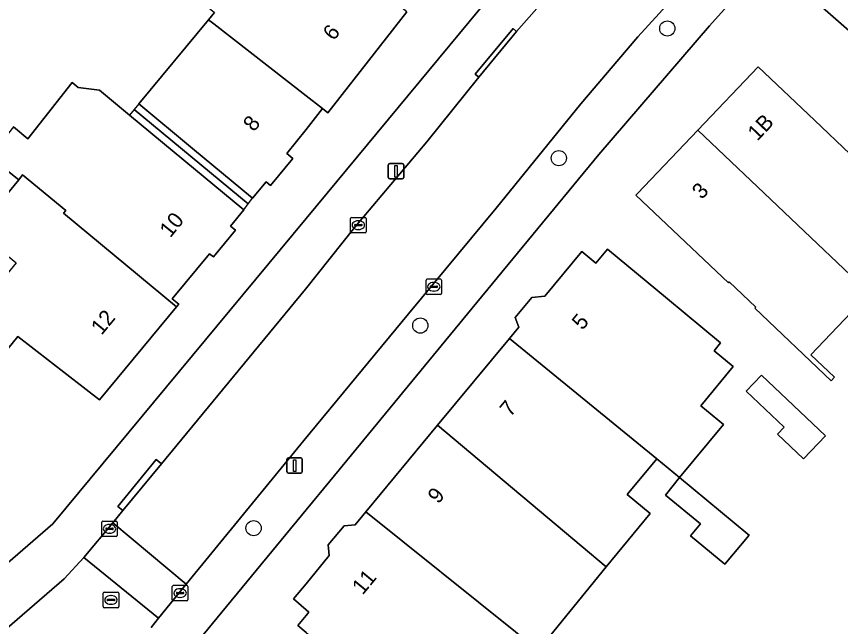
# Model space of a CAD drawing. Extents: x 161772 to 163126, y 383092 to 383917.
# Drawn here: x 162481.4 to 162534.3, y 383548.4 to 383587.6 of the extents above; entities that cross this region are included whole.
import ezdxf

# ---------------------------------------------------------------- set-up
doc = ezdxf.new("R2010")
doc.units = 0
for name, color, linetype in [('IMGEO_Boom', 7, 'Continuous'), ('IMGEO_Erf', 7, 'Continuous'), ('IMGEO_Kolk', 7, 'Continuous'), ('IMGEO_Lichtmast', 7, 'Continuous'), ('IMGEO_Pand', 7, 'Continuous'), ('IMGEO_Pand_nummerreeks', 7, 'Continuous'), ('IMGEO_Pand_overbouw', 7, 'Continuous'), ('IMGEO_Rijbaan_lokaal_open', 7, 'Continuous'), ('IMGEO_Rioolput', 7, 'Continuous'), ('IMGEO_Voetpad_open', 7, 'Continuous')]:
    doc.layers.add(name, color=color, linetype=linetype)

msp = doc.modelspace()

# ---------------------------------------------------------------- linework, layer by layer
at = {"layer": 'IMGEO_Boom'}
for centre in [(162523.191, 383586.794), (162516.227, 383578.471), (162507.334, 383567.722), (162496.634, 383554.71)]:
    msp.add_circle(centre, 0.489, dxfattribs=at)
at = {"layer": 'IMGEO_Erf'}
for points in [[(162462.704, 383536.779), (162483.744, 383554.98), (162500, 383574.599), (162526.947, 383607.122), (162543.804, 383623.317), (162548.918, 383628.126), (162539.791, 383641.093), (162527.133, 383641.683), (162527.105, 383641.456), (162500, 383642.583), (162442.25, 383644.984), (162375.184, 383528.714), (162418.191, 383500), (162425.357, 383495.215)], [(162539.703, 383602.034), (162533.89, 383595.873), (162525.907, 383586.964), (162518.786, 383578.702), (162510.666, 383568.842), (162501.518, 383557.733), (162500, 383555.89), (162492.693, 383547.017)], [(162506.472, 383587.872), (162501.403, 383581.38), (162501.06, 383581.651), (162500, 383580.313), (162498.774, 383578.766), (162499.16, 383578.446), (162497.723, 383576.713), (162497.439, 383576.949), (162496.57, 383575.901), (162492.72, 383579.092), (162489.265, 383581.957), (162493.744, 383587.36), (162494.132, 383587.828)], [(162481.216, 383580.476), (162482.14, 383579.711), (162484.991, 383583.321), (162485.376, 383583.002), (162486.746, 383582.836), (162488.671, 383581.24), (162492.165, 383578.343), (162496.014, 383575.152), (162495.15, 383574.109), (162495.473, 383573.841), (162494.053, 383572.128), (162493.8, 383572.337), (162491.399, 383569.44), (162491.827, 383569.086), (162491.689, 383568.92), (162486.735, 383562.944), (162481.496, 383567.012), (162479.628, 383564.76)], [(162478.866, 383573.829), (162481.566, 383577.087), (162479.686, 383578.547)], [(162500, 383548.023), (162499.466, 383548.469), (162500, 383549.112), (162500.175, 383549.323), (162500, 383549.474), (162499.194, 383550.167), (162500, 383551.142), (162501.492, 383552.948), (162501.427, 383553.635), (162502.443, 383554.862), (162503.146, 383554.928), (162503.842, 383555.768), (162508.448, 383561.33), (162513.053, 383566.891), (162513.652, 383567.614), (162513.423, 383568.23), (162514.493, 383569.521), (162515.331, 383569.6), (162517.71, 383572.472), (162518.611, 383571.727), (162519.349, 383572.618), (162523.2, 383569.429), (162526.612, 383566.602), (162526.193, 383566.096), (162527.417, 383565.082), (162525.341, 383562.575), (162526.799, 383561.367), (162523.978, 383557.962), (162522.513, 383559.16), (162520.617, 383556.87), (162522.095, 383555.647), (162519.266, 383552.231), (162515.623, 383547.758)]]:
    msp.add_lwpolyline(points, dxfattribs=at)
for points in [[(162544.222, 383584.846), (162541.032, 383581.223), (162536.404, 383585.298), (162532.651, 383588.602), (162539.681, 383596.585), (162543.434, 383593.281), (162548.075, 383589.194), (162546.474, 383587.375), (162546.712, 383586.669), (162544.973, 383584.695)], [(162537.296, 383568.725), (162536.236, 383569.732), (162536.189, 383569.682), (162537.629, 383568.313), (162537.354, 383568.023), (162535.847, 383569.455), (162532.415, 383565.845), (162533.932, 383564.403), (162533.718, 383564.179), (162528.818, 383568.836), (162528.88, 383568.901), (162527.172, 383570.524), (162527.11, 383570.459), (162521.181, 383576.094), (162521.277, 383576.194), (162525.149, 383580.269), (162529.02, 383584.344), (162532.645, 383580.901), (162534.926, 383578.733), (162537.177, 383576.596), (162536.914, 383576.319), (162540.936, 383572.495)], [(162530.268, 383560.751), (162530.684, 383561.191), (162528.246, 383563.502), (162529.232, 383564.543), (162533.346, 383560.643), (162531.943, 383559.163)], [(162523.978, 383557.962), (162528.354, 383554.327), (162528.437, 383554.27), (162526.88, 383552.39), (162524.68, 383554.212), (162525.322, 383554.987), (162523.084, 383556.841)]]:
    msp.add_lwpolyline(points, close=True, dxfattribs=at)
at = {"layer": 'IMGEO_Kolk'}
for p, q in [((162502.858, 383573.743), (162502.858, 383574.595)), ((162502.933, 383574.669), (162503.785, 383574.669)), ((162503.117, 383574.163), (162503.117, 383574.175)), ((162503.16, 383574.212), (162503.558, 383574.212)), ((162503.346, 383574.449), (162503.371, 383574.449)), ((162503.601, 383574.175), (162503.601, 383574.163)), ((162503.859, 383574.595), (162503.859, 383573.743)), ((162503.785, 383573.669), (162502.933, 383573.669)), ((162503.555, 383574.126), (162503.157, 383574.126)), ((162503.369, 383573.889), (162503.344, 383573.889)), ((162507.704, 383569.785), (162507.704, 383570.637)), ((162507.779, 383570.711), (162508.631, 383570.711)), ((162508.192, 383570.491), (162508.217, 383570.491)), ((162508.705, 383570.637), (162508.705, 383569.785)), ((162507.963, 383570.205), (162507.963, 383570.217)), ((162508.401, 383570.168), (162508.003, 383570.168)), ((162508.006, 383570.254), (162508.404, 383570.254)), ((162508.215, 383569.931), (162508.19, 383569.931)), ((162508.447, 383570.217), (162508.447, 383570.205)), ((162508.631, 383569.711), (162507.779, 383569.711)), ((162486.956, 383555.169), (162487.808, 383555.169)), ((162486.881, 383554.243), (162486.881, 383555.095)), ((162487.14, 383554.663), (162487.14, 383554.675)), ((162487.578, 383554.626), (162487.18, 383554.626)), ((162487.183, 383554.712), (162487.581, 383554.712)), ((162487.369, 383554.949), (162487.394, 383554.949)), ((162487.624, 383554.675), (162487.624, 383554.663)), ((162487.882, 383555.095), (162487.882, 383554.243)), ((162487.808, 383554.169), (162486.956, 383554.169)), ((162487.392, 383554.389), (162487.367, 383554.389)), ((162491.415, 383550.116), (162491.415, 383550.968)), ((162491.49, 383551.042), (162492.342, 383551.042)), ((162492.416, 383550.968), (162492.416, 383550.116)), ((162491.674, 383550.536), (162491.674, 383550.548)), ((162492.112, 383550.499), (162491.714, 383550.499)), ((162491.717, 383550.585), (162492.115, 383550.585)), ((162491.903, 383550.822), (162491.928, 383550.822)), ((162492.158, 383550.548), (162492.158, 383550.536)), ((162492.342, 383550.042), (162491.49, 383550.042)), ((162491.926, 383550.262), (162491.901, 383550.262))]:
    msp.add_line(p, q, dxfattribs=at)
for points in [[(162502.858, 383573.743), (162502.858, 383574.595)], [(162502.933, 383574.669), (162503.785, 383574.669)], [(162503.859, 383574.595), (162503.859, 383573.743)], [(162503.785, 383573.669), (162502.933, 383573.669)], [(162507.704, 383569.785), (162507.704, 383570.637)], [(162507.779, 383570.711), (162508.631, 383570.711)], [(162508.705, 383570.637), (162508.705, 383569.785)], [(162508.631, 383569.711), (162507.779, 383569.711)], [(162486.956, 383555.169), (162487.808, 383555.169)], [(162486.881, 383554.243), (162486.881, 383555.095)], [(162487.882, 383555.095), (162487.882, 383554.243)], [(162487.808, 383554.169), (162486.956, 383554.169)], [(162491.415, 383550.116), (162491.415, 383550.968)], [(162491.49, 383551.042), (162492.342, 383551.042)], [(162492.416, 383550.968), (162492.416, 383550.116)], [(162492.342, 383550.042), (162491.49, 383550.042)]]:
    msp.add_lwpolyline(points, dxfattribs=at)
for centre, radius, start, end in [((162502.935, 383574.593), 0.0765, 91.552, 178.448), ((162502.935, 383574.593), 0.0765, 91.552, 178.448), ((162503.157, 383574.172), 0.0403, 85.8775, 175.7526), ((162503.154, 383574.162), 0.0366, 178.938, 274.7102), ((162503.558, 383574.169), 0.043, 264.8664, 352.4533), ((162503.562, 383574.174), 0.0386, 1.7309, 96.639), ((162503.783, 383574.593), 0.0765, 1.552, 88.448), ((162503.783, 383574.593), 0.0765, 1.552, 88.448), ((162502.935, 383573.745), 0.0765, 181.552, 268.448), ((162502.935, 383573.745), 0.0765, 181.552, 268.448), ((162503.783, 383573.745), 0.0765, 271.552, 358.448), ((162503.783, 383573.745), 0.0765, 271.552, 358.448), ((162507.781, 383570.635), 0.0765, 91.552, 178.448), ((162507.781, 383570.635), 0.0765, 91.552, 178.448), ((162508.629, 383570.635), 0.0765, 1.552, 88.448), ((162508.629, 383570.635), 0.0765, 1.552, 88.448), ((162508.003, 383570.214), 0.0403, 85.8775, 175.7526), ((162508, 383570.204), 0.0366, 178.938, 274.7102), ((162508.404, 383570.211), 0.043, 264.8664, 352.4533), ((162508.408, 383570.216), 0.0386, 1.7309, 96.639), ((162507.781, 383569.787), 0.0765, 181.552, 268.448), ((162507.781, 383569.787), 0.0765, 181.552, 268.448), ((162508.629, 383569.787), 0.0765, 271.552, 358.448), ((162508.629, 383569.787), 0.0765, 271.552, 358.448), ((162486.958, 383555.093), 0.0765, 91.552, 178.448), ((162486.958, 383555.093), 0.0765, 91.552, 178.448), ((162487.806, 383555.093), 0.0765, 1.552, 88.448), ((162487.806, 383555.093), 0.0765, 1.552, 88.448), ((162487.18, 383554.672), 0.0403, 85.8775, 175.7526), ((162487.177, 383554.662), 0.0366, 178.938, 274.7102), ((162487.581, 383554.669), 0.043, 264.8664, 352.4533), ((162487.585, 383554.674), 0.0386, 1.7309, 96.639), ((162486.958, 383554.245), 0.0765, 181.552, 268.448), ((162486.958, 383554.245), 0.0765, 181.552, 268.448), ((162487.806, 383554.245), 0.0765, 271.552, 358.448), ((162487.806, 383554.245), 0.0765, 271.552, 358.448), ((162491.492, 383550.966), 0.0765, 91.552, 178.448), ((162491.492, 383550.966), 0.0765, 91.552, 178.448), ((162492.34, 383550.966), 0.0765, 1.552, 88.448), ((162492.34, 383550.966), 0.0765, 1.552, 88.448), ((162491.714, 383550.545), 0.0403, 85.8775, 175.7526), ((162491.711, 383550.535), 0.0366, 178.938, 274.7102), ((162492.115, 383550.542), 0.043, 264.8664, 352.4533), ((162492.119, 383550.547), 0.0386, 1.7309, 96.639), ((162491.492, 383550.118), 0.0765, 181.552, 268.448), ((162491.492, 383550.118), 0.0765, 181.552, 268.448), ((162492.34, 383550.118), 0.0765, 271.552, 358.448), ((162492.34, 383550.118), 0.0765, 271.552, 358.448)]:
    msp.add_arc(centre, radius, start, end, dxfattribs=at)
for centre, major_axis, ratio, start_param, end_param in [((162503.345, 383574.169), (-0.387, 0.002), 0.722429, 4.712389, 7.853982), ((162503.37, 383574.169), (-0.39, 0.002), 0.717154, 1.570796, 4.712389), ((162508.191, 383570.211), (-0.387, 0.002), 0.722429, 4.712389, 7.853982), ((162508.216, 383570.211), (-0.39, 0.002), 0.717154, 1.570796, 4.712389), ((162487.368, 383554.669), (-0.387, 0.002), 0.722429, 4.712389, 7.853982), ((162487.393, 383554.669), (-0.39, 0.002), 0.717154, 1.570796, 4.712389), ((162491.902, 383550.542), (-0.387, 0.002), 0.722429, 4.712389, 7.853982), ((162491.927, 383550.542), (-0.39, 0.002), 0.717154, 1.570796, 4.712389)]:
    msp.add_ellipse(centre, major_axis=major_axis, ratio=ratio, start_param=start_param, end_param=end_param, dxfattribs=at)
at = {"layer": 'IMGEO_Lichtmast'}
for p, q in [((162505.279, 383577.234), (162505.279, 383578.034)), ((162505.279, 383578.034), (162505.279, 383577.234)), ((162505.379, 383578.134), (162506.169, 383578.134)), ((162506.169, 383578.134), (162505.379, 383578.134)), ((162506.269, 383578.034), (162506.269, 383577.234)), ((162506.269, 383577.234), (162506.269, 383578.034)), ((162506.169, 383577.134), (162505.379, 383577.134)), ((162505.379, 383577.134), (162506.169, 383577.134)), ((162498.771, 383558.334), (162498.771, 383559.134)), ((162498.771, 383559.134), (162498.771, 383558.334)), ((162498.871, 383559.234), (162499.661, 383559.234)), ((162499.661, 383559.234), (162498.871, 383559.234)), ((162499.761, 383559.134), (162499.761, 383558.334)), ((162499.761, 383558.334), (162499.761, 383559.134)), ((162499.661, 383558.234), (162498.871, 383558.234)), ((162498.871, 383558.234), (162499.661, 383558.234))]:
    msp.add_line(p, q, dxfattribs=at)
for points in [[(162505.699, 383578.009), (162505.849, 383578.009), (162505.849, 383577.259), (162505.699, 383577.259), (162505.699, 383578.009)], [(162499.191, 383559.109), (162499.341, 383559.109), (162499.341, 383558.359), (162499.191, 383558.359), (162499.191, 383559.109)]]:
    msp.add_lwpolyline(points, dxfattribs=at)
for centre, start, end in [((162505.379, 383578.034), 90, 180), ((162505.379, 383578.034), 90, 180), ((162506.169, 383578.034), 0, 90), ((162506.169, 383578.034), 360, 90), ((162505.379, 383577.234), 180, 270), ((162505.379, 383577.234), 180, 270), ((162506.169, 383577.234), 270, 0), ((162506.169, 383577.234), 270, 0), ((162498.871, 383559.134), 90, 180), ((162498.871, 383559.134), 90, 180), ((162499.661, 383559.134), 0, 90), ((162499.661, 383559.134), 360, 90), ((162498.871, 383558.334), 180, 270), ((162498.871, 383558.334), 180, 270), ((162499.661, 383558.334), 270, 0), ((162499.661, 383558.334), 270, 0)]:
    msp.add_arc(centre, 0.1, start, end, dxfattribs=at)
at = {"layer": 'IMGEO_Pand'}
for points in [[(162504.664, 383590.902), (162501.958, 383593.04), (162503.741, 383595.297), (162500, 383598.256), (162499.797, 383598.417), (162497.67, 383600.132), (162498.544, 383601.187), (162492.309, 383605.412), (162489.661, 383602.217), (162495.432, 383597.433), (162494.746, 383596.605), (162496.763, 383594.932), (162492.201, 383589.429), (162494.132, 383587.828), (162493.744, 383587.36), (162494.073, 383587.101), (162500, 383582.475), (162501.06, 383581.651), (162501.403, 383581.38), (162506.472, 383587.872), (162503.885, 383589.916)], [(162541.032, 383581.223), (162544.222, 383584.846), (162544.973, 383584.695), (162546.712, 383586.669), (162546.474, 383587.375), (162548.075, 383589.194), (162543.434, 383593.281), (162539.681, 383596.585), (162532.651, 383588.602), (162536.404, 383585.298)], [(162493.744, 383587.36), (162489.265, 383581.957), (162492.72, 383579.092), (162496.57, 383575.901), (162497.439, 383576.949), (162497.723, 383576.713), (162499.16, 383578.446), (162498.774, 383578.766), (162500, 383580.313), (162501.06, 383581.651), (162500, 383582.475), (162494.073, 383587.101)], [(162536.236, 383569.732), (162537.296, 383568.725), (162540.936, 383572.495), (162536.914, 383576.319), (162537.177, 383576.596), (162534.926, 383578.733), (162532.645, 383580.901), (162529.02, 383584.344), (162525.149, 383580.269)], [(162491.689, 383568.92), (162491.827, 383569.086), (162491.399, 383569.44), (162493.8, 383572.337), (162494.053, 383572.128), (162495.473, 383573.841), (162495.15, 383574.109), (162496.014, 383575.152), (162492.165, 383578.343), (162488.671, 383581.24), (162486.746, 383582.836), (162485.376, 383583.002), (162484.991, 383583.321), (162482.14, 383579.711), (162481.216, 383580.476), (162479.686, 383578.547), (162481.566, 383577.087), (162481.806, 383577.39), (162484.569, 383575.1), (162484.436, 383574.932)], [(162525.149, 383580.269), (162521.277, 383576.194), (162521.181, 383576.094), (162527.11, 383570.459), (162527.172, 383570.524), (162528.88, 383568.901), (162528.818, 383568.836), (162533.718, 383564.179), (162533.932, 383564.403), (162532.415, 383565.845), (162535.847, 383569.455), (162537.354, 383568.023), (162537.629, 383568.313), (162536.189, 383569.682), (162536.236, 383569.732)], [(162491.689, 383568.92), (162484.436, 383574.932), (162484.569, 383575.1), (162481.806, 383577.39), (162481.566, 383577.087), (162478.866, 383573.829), (162481.383, 383571.745), (162479.42, 383569.376), (162477.097, 383571.301), (162476.648, 383571.673), (162473.721, 383568.14), (162476.216, 383565.042), (162477.407, 383566.479), (162479.628, 383564.76), (162481.496, 383567.012), (162486.735, 383562.944)], [(162523.2, 383569.429), (162519.349, 383572.618), (162518.611, 383571.727), (162517.71, 383572.472), (162515.331, 383569.6), (162514.493, 383569.521), (162513.423, 383568.23), (162513.652, 383567.614), (162513.053, 383566.891), (162522.513, 383559.16), (162523.978, 383557.962), (162526.799, 383561.367), (162525.341, 383562.575), (162527.417, 383565.082), (162526.193, 383566.096), (162526.612, 383566.602)], [(162522.513, 383559.16), (162513.053, 383566.891), (162508.448, 383561.33), (162519.266, 383552.231), (162522.095, 383555.647), (162520.617, 383556.87)], [(162531.943, 383559.163), (162533.346, 383560.643), (162529.232, 383564.543), (162528.246, 383563.502), (162530.684, 383561.191), (162530.268, 383560.751)], [(162508.448, 383561.33), (162503.842, 383555.768), (162513.455, 383548.049), (162514.883, 383546.865), (162515.623, 383547.758), (162519.266, 383552.231)], [(162523.978, 383557.962), (162523.084, 383556.841), (162525.322, 383554.987), (162524.68, 383554.212), (162526.88, 383552.39), (162528.437, 383554.27), (162528.354, 383554.327)], [(162503.842, 383555.768), (162503.146, 383554.928), (162502.443, 383554.862), (162501.427, 383553.635), (162501.492, 383552.948), (162500, 383551.142), (162499.194, 383550.167), (162500, 383549.474), (162500.175, 383549.323), (162500, 383549.112), (162499.466, 383548.469), (162500, 383548.023), (162503.265, 383545.293), (162506.761, 383542.365), (162509.345, 383540.203), (162511.12, 383542.324), (162514.671, 383546.609), (162514.883, 383546.865), (162513.455, 383548.049)]]:
    msp.add_lwpolyline(points, close=True, dxfattribs=at)
at = {"layer": 'IMGEO_Pand_overbouw'}
for points in [[(162488.671, 383581.24), (162492.165, 383578.343), (162496.014, 383575.152), (162496.292, 383575.527), (162488.968, 383581.599)], [(162489.265, 383581.957), (162488.968, 383581.599), (162496.292, 383575.527), (162496.57, 383575.901), (162492.72, 383579.092)]]:
    msp.add_lwpolyline(points, close=True, dxfattribs=at)
at = {"layer": 'IMGEO_Rijbaan_lokaal_open'}
for points in [[(162537.203, 383612.786), (162532.418, 383607.776), (162527.435, 383602.384), (162520.458, 383594.506), (162513.52, 383586.607), (162511.095, 383583.664), (162507.749, 383579.508), (162503.132, 383574.038), (162499.96, 383570.06), (162490.713, 383558.838), (162488.243, 383555.841), (162487.591, 383555.051), (162492.315, 383551.109), (162499.866, 383560.331), (162506.576, 383568.47), (162512.205, 383575.261), (162517.639, 383581.965), (162521.297, 383586.253), (162525.402, 383590.777), (162527.89, 383593.519), (162530.565, 383596.403), (162537.488, 383604.096)], [(162490.049, 383548.342), (162490.534, 383548.934), (162485.735, 383552.822), (162484.483, 383551.467), (162468.577, 383537.721)]]:
    msp.add_lwpolyline(points, dxfattribs=at)
msp.add_lwpolyline([(162487.591, 383555.051), (162485.735, 383552.822), (162490.534, 383548.934), (162492.315, 383551.109)], close=True, dxfattribs=at)
at = {"layer": 'IMGEO_Rioolput'}
for p, q in [((162486.973, 383549.679), (162486.973, 383550.531)), ((162487.048, 383550.605), (162487.9, 383550.605)), ((162487.461, 383550.385), (162487.486, 383550.385)), ((162487.974, 383550.531), (162487.974, 383549.679)), ((162487.232, 383550.099), (162487.232, 383550.111)), ((162487.67, 383550.062), (162487.272, 383550.062)), ((162487.275, 383550.148), (162487.673, 383550.148)), ((162487.484, 383549.825), (162487.459, 383549.825)), ((162487.716, 383550.111), (162487.716, 383550.099)), ((162487.9, 383549.605), (162487.048, 383549.605))]:
    msp.add_line(p, q, dxfattribs=at)
for points in [[(162486.973, 383549.679), (162486.973, 383550.531)], [(162487.048, 383550.605), (162487.9, 383550.605)], [(162487.974, 383550.531), (162487.974, 383549.679)], [(162487.9, 383549.605), (162487.048, 383549.605)]]:
    msp.add_lwpolyline(points, dxfattribs=at)
for centre, radius, start, end in [((162487.05, 383550.529), 0.0765, 91.552, 178.448), ((162487.05, 383550.529), 0.0765, 91.552, 178.448), ((162487.898, 383550.529), 0.0765, 1.552, 88.448), ((162487.898, 383550.529), 0.0765, 1.552, 88.448), ((162487.272, 383550.108), 0.0403, 85.8775, 175.7526), ((162487.269, 383550.098), 0.0366, 178.938, 274.7102), ((162487.673, 383550.105), 0.043, 264.8664, 352.4533), ((162487.677, 383550.11), 0.0386, 1.7309, 96.639), ((162487.05, 383549.681), 0.0765, 181.552, 268.448), ((162487.05, 383549.681), 0.0765, 181.552, 268.448), ((162487.898, 383549.681), 0.0765, 271.552, 358.448), ((162487.898, 383549.681), 0.0765, 271.552, 358.448)]:
    msp.add_arc(centre, radius, start, end, dxfattribs=at)
for centre, major_axis, ratio, start_param, end_param in [((162487.46, 383550.105), (-0.387, 0.002), 0.722429, 4.712389, 7.853982), ((162487.485, 383550.105), (-0.39, 0.002), 0.717154, 1.570796, 4.712389)]:
    msp.add_ellipse(centre, major_axis=major_axis, ratio=ratio, start_param=start_param, end_param=end_param, dxfattribs=at)
at = {"layer": 'IMGEO_Voetpad_open'}
for points in [[(162549.66, 383629.858), (162548.918, 383628.126), (162543.804, 383623.317), (162526.947, 383607.122), (162500, 383574.599), (162483.744, 383554.98), (162462.704, 383536.779), (162467.807, 383530.859), (162432.045, 383500), (162426.613, 383495.312), (162428.778, 383494.029), (162435.72, 383500), (162437.045, 383501.14), (162437.192, 383501.282), (162438.691, 383502.574), (162438.438, 383502.865), (162441.394, 383505.425), (162441.654, 383505.126), (162443.112, 383506.379), (162469.395, 383528.971)], [(162468.577, 383537.721), (162484.483, 383551.467), (162485.735, 383552.822), (162487.591, 383555.051), (162488.243, 383555.841), (162487.915, 383556.108), (162490.371, 383559.116), (162490.713, 383558.838), (162499.96, 383570.06), (162503.132, 383574.038), (162507.749, 383579.508), (162511.095, 383583.664), (162510.859, 383583.859), (162513.286, 383586.801), (162513.52, 383586.607), (162520.458, 383594.506), (162527.435, 383602.384), (162532.418, 383607.776), (162537.203, 383612.786), (162540.103, 383615.776), (162538.984, 383617.258), (162540.462, 383618.813), (162542.308, 383616.755)], [(162497.729, 383541.518), (162492.693, 383547.017), (162500, 383555.89), (162501.518, 383557.733), (162510.666, 383568.842), (162518.786, 383578.702), (162525.907, 383586.964), (162533.89, 383595.873), (162539.703, 383602.034), (162537.488, 383604.096), (162530.565, 383596.403), (162527.89, 383593.519), (162528.327, 383593.13), (162525.868, 383590.36), (162525.402, 383590.777), (162521.297, 383586.253), (162517.639, 383581.965), (162512.205, 383575.261), (162506.576, 383568.47), (162499.866, 383560.331), (162492.315, 383551.109), (162490.534, 383548.934), (162490.049, 383548.342)]]:
    msp.add_lwpolyline(points, dxfattribs=at)
for points in [[(162513.52, 383586.607), (162513.286, 383586.801), (162510.859, 383583.859), (162511.095, 383583.664)], [(162490.713, 383558.838), (162490.371, 383559.116), (162487.915, 383556.108), (162488.243, 383555.841)]]:
    msp.add_lwpolyline(points, close=True, dxfattribs=at)

# ---------------------------------------------------------------- texts
at = {"layer": 'IMGEO_Pand_nummerreeks'}
for s, rotation, p in [('6', 52.0188, (162501.782, 383585.961)), ('8', 52.0148, (162496.661, 383580.114)), ('1B', 46.467, (162528.971, 383579.53)), ('3', 46.4669, (162525.401, 383575.773)), ('10', 51.0636, (162491.287, 383573.311)), ('12', 50.3397, (162486.87, 383567.056)), ('5', 50.3057, (162517.744, 383567.377)), ('7', 50.3057, (162513.115, 383561.8)), ('9', 50.3057, (162508.486, 383556.224)), ('11', 50.3057, (162503.635, 383550.382))]:
    msp.add_text(s, height=1, rotation=rotation, dxfattribs=at).set_placement(p)

doc.saveas('drawing.dxf')
